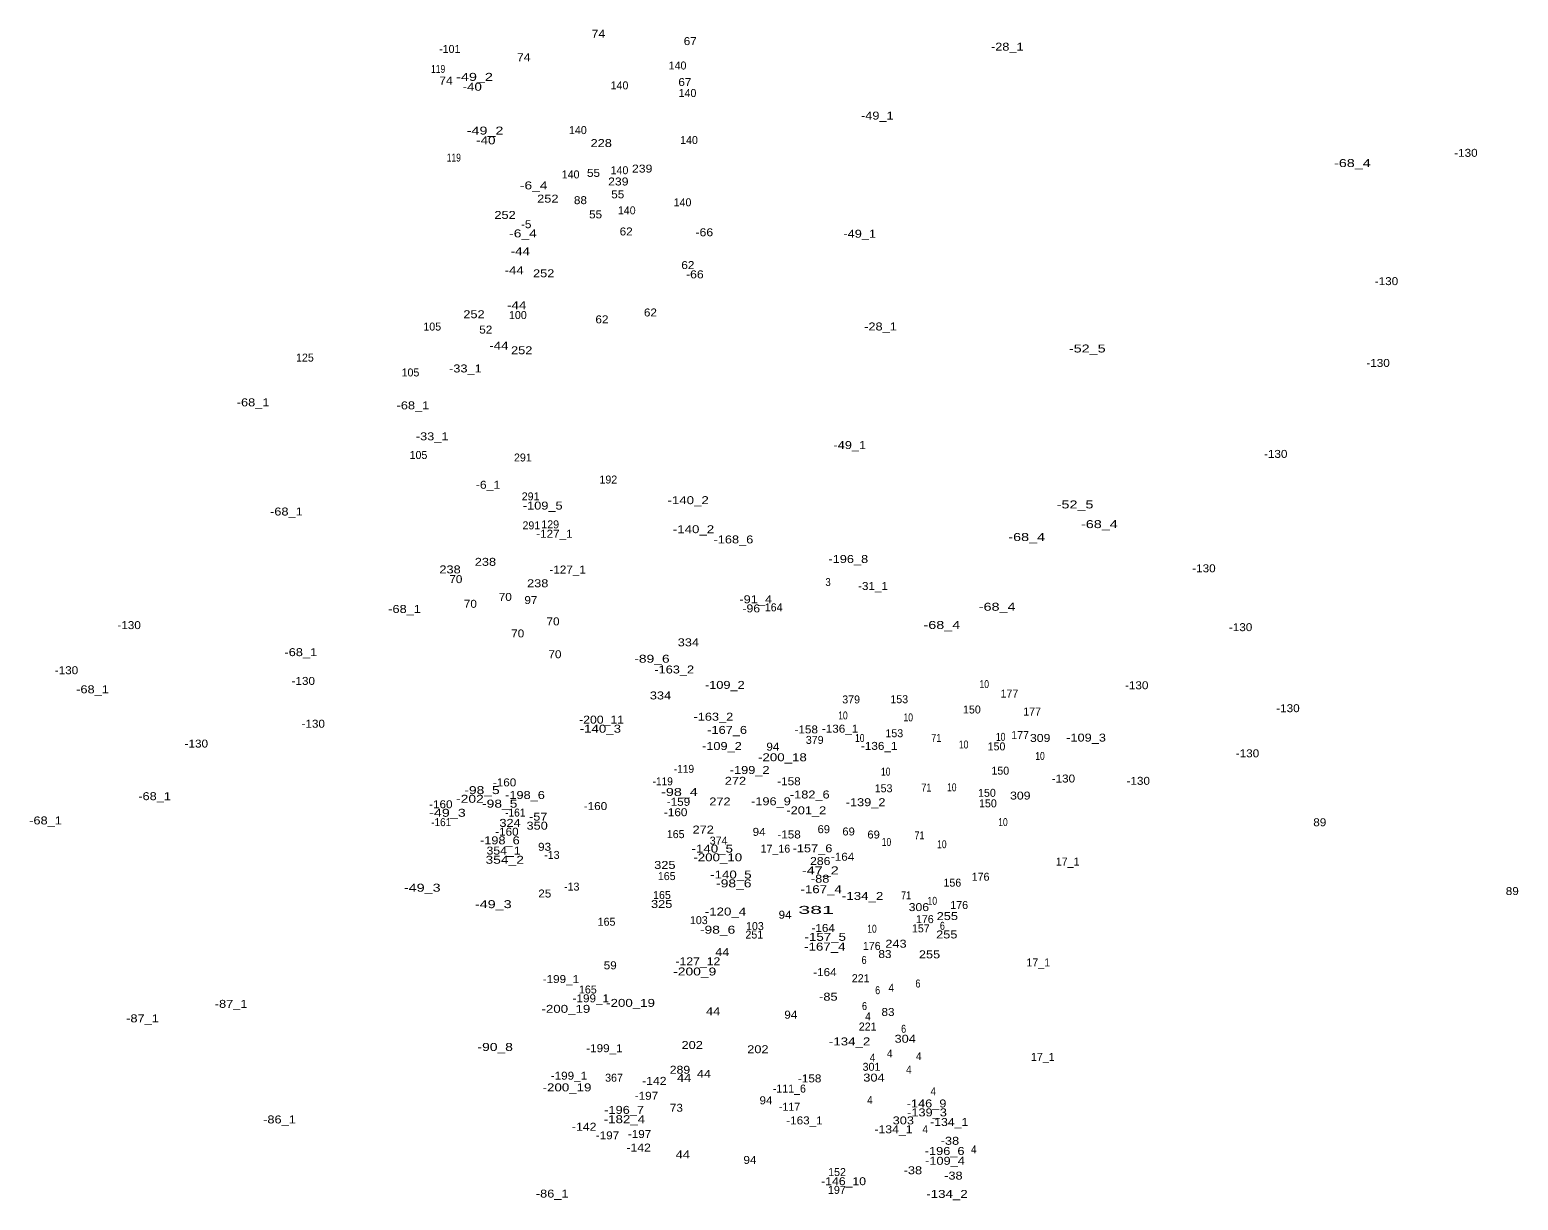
# Model space of a CAD drawing. Extents: x -662996 to -659766, y -998554 to -993949.
# Drawn here: x -661831 to -661083, y -996273 to -995685 of the extents above; entities that cross this region are included whole.
import ezdxf
from ezdxf.enums import TextEntityAlignment as Align

# ---------------------------------------------------------------- set-up
doc = ezdxf.new("R2010")
doc.units = 0
doc.header["$LTSCALE"] = 1.6
doc.layers.add('24', color=7, linetype='Continuous')

msp = doc.modelspace()

# ---------------------------------------------------------------- texts
at = {"layer": '24'}
for s, width, p in [('74', 1.15, (-661545.52, -995689.19)), ('67', 1.1, (-661499.35, -995692.88)), ('-28_1', 1.2, (-661339.949, -995695.69)), ('74', 1.15, (-661583.06, -995700.99)), ('119', 0.8, (-661626.101, -995706.87)), ('-49_2', 1.35, (-661607.79, -995710.85)), ('74', 1.15, (-661622.13, -995712.7)), ('-40', 1.25, (-661608.94, -995715.84)), ('67', 1.1, (-661502.04, -995713.44)), ('-49_1', 1.2, (-661405.3, -995730.32)), ('-49_2', 1.35, (-661602.5, -995737.84)), ('-40', 1.25, (-661602.11, -995742.74)), ('228', 1.2, (-661544.1, -995744.12)), ('-130', 1.1, (-661109.37, -995749.03)), ('119', 0.8, (-661618.221, -995751.43)), ('239', 1.15, (-661523.51, -995756.95)), ('-68_4', 1.35, (-661166.44, -995754.17)), ('55', 1.1, (-661547.98, -995759.12)), ('239', 1.15, (-661535.51, -995763.43)), ('-6_4', 1.3, (-661578.05, -995765.4)), ('252', 1.2, (-661570.939, -995772.05)), ('55', 1.1, (-661535.79, -995769.87)), ('88', 1.1, (-661554.549, -995772.82)), ('252', 1.2, (-661592.449, -995780.24)), ('-5', 1.1, (-661581.8, -995784.9)), ('55', 1.1, (-661546.929, -995779.96)), ('-6_4', 1.3, (-661583.43, -995789.51)), ('62', 1.1, (-661531.56, -995788.54)), ('-66', 1.15, (-661492.27, -995788.95)), ('-49_1', 1.2, (-661414.14, -995789.69)), ('-44', 1.25, (-661584.78, -995798.52)), ('-44', 1.25, (-661587.85, -995808.03)), ('252', 1.2, (-661573.03, -995809.57)), ('62', 1.1, (-661500.55, -995805.44)), ('-66', 1.15, (-661497.03, -995810.1)), ('-130', 1.1, (-661149.301, -995813.51)), ('252', 1.2, (-661608.069, -995830.14)), ('-44', 1.25, (-661586.6, -995825.61)), ('62', 1.1, (-661519.37, -995829.26)), ('52', 1.1, (-661602.14, -995837.85)), ('62', 1.1, (-661543.75, -995832.72)), ('-28_1', 1.2, (-661403.699, -995836.29)), ('-44', 1.25, (-661595.53, -995845.87)), ('252', 1.2, (-661584.079, -995848.24)), ('-52_5', 1.35, (-661299.73, -995847.36)), ('-33_1', 1.2, (-661612.39, -995857.39)), ('-130', 1.1, (-661153.53, -995854.62)), ('-68_1', 1.2, (-661719.13, -995874.42)), ('-68_1', 1.2, (-661638.78, -995875.94)), ('-33_1', 1.2, (-661629.1, -995891.49)), ('-49_1', 1.2, (-661419.13, -995895.89)), ('-130', 1.1, (-661204.99, -995900.33)), ('-6_1', 1.15, (-661601, -995915.84)), ('-68_1', 1.2, (-661702.38, -995929.28)), ('-109_5', 1.2, (-661573.51, -995926.31)), ('-140_2', 1.25, (-661500.41, -995923.58)), ('-52_5', 1.35, (-661305.87, -995925.73)), ('-68_4', 1.35, (-661293.64, -995935.62)), ('-127_1', 1.1, (-661567.64, -995940.45)), ('-140_2', 1.25, (-661497.72, -995938.18)), ('-168_6', 1.2, (-661477.64, -995943.31)), ('-68_4', 1.35, (-661330.19, -995942.1)), ('238', 1.2, (-661620.11, -995958.38)), ('238', 1.2, (-661602.309, -995954.57)), ('-127_1', 1.1, (-661560.981, -995958.43)), ('-196_8', 1.2, (-661419.89, -995953.15)), ('-130', 1.1, (-661241.081, -995957.82)), ('70', 1.1, (-661617.19, -995963.26)), ('238', 1.2, (-661576.03, -995965.33)), ('3', 0.9, (-661430.049, -995964.72)), ('-31_1', 1.1, (-661407.459, -995966.71)), ('70', 1.1, (-661592.33, -995972.2)), ('97', 1.1, (-661579.46, -995973.78)), ('-91_4', 1.2, (-661466.44, -995973.4)), ('-68_1', 1.2, (-661642.971, -995978.25)), ('70', 1.1, (-661609.89, -995975.65)), ('-96', 1.15, (-661468.669, -995977.96)), ('-68_4', 1.35, (-661345.05, -995977.15)), ('-130', 1.1, (-661781.451, -995986.37)), ('70', 1.1, (-661568.33, -995984.49)), ('-68_4', 1.35, (-661372.84, -995986.29)), ('-130', 1.1, (-661222.65, -995987.4)), ('70', 1.1, (-661586.09, -995990.54)), ('334', 1.2, (-661500.29, -995995.01)), ('-68_1', 1.2, (-661695.14, -995999.96)), ('70', 1.1, (-661567.37, -996001.01)), ('-89_6', 1.3, (-661518.6, -996003.26)), ('-130', 1.1, (-661812.941, -996009.03)), ('-163_2', 1.2, (-661507.4, -996008.66)), ('-68_1', 1.2, (-661799.861, -996018.63)), ('-130', 1.1, (-661693.9, -996014.41)), ('-109_2', 1.2, (-661481.961, -996016.41)), ('10', 0.8, (-661351.53, -996016.01)), ('-130', 1.1, (-661274.88, -996016.6)), ('334', 1.2, (-661514.299, -996021.71)), ('-200_11', 1.15, (-661543.92, -996033.87)), ('-163_2', 1.2, (-661487.721, -996032.39)), ('10', 0.8, (-661422.57, -996031.76)), ('10', 0.8, (-661389.74, -996032.73)), ('-130', 1.1, (-661198.841, -996028.12)), ('-130', 1.1, (-661688.9, -996035.92)), ('-140_3', 1.25, (-661544.53, -996038.42)), ('-167_6', 1.2, (-661480.799, -996039.03)), ('-158', 1.1, (-661441.03, -996038.78)), ('-136_1', 1.1, (-661424.03, -996038.41)), ('-130', 1.1, (-661747.66, -996045.91)), ('-109_2', 1.2, (-661483.421, -996047.13)), ('94', 1.1, (-661457.8, -996047.45)), ('10', 0.8, (-661414.12, -996043.1)), ('-136_1', 1.1, (-661404.351, -996047.06)), ('71', 0.85, (-661375.66, -996043.04)), ('10', 0.8, (-661361.9, -996046.36)), ('10', 0.8, (-661343.27, -996042.52)), ('309', 1.15, (-661323.41, -996043.08)), ('-109_3', 1.2, (-661300.351, -996042.9)), ('-200_18', 1.25, (-661453, -996052.77)), ('10', 0.8, (-661323.49, -996052.12)), ('-130', 1.1, (-661219.191, -996050.79)), ('-119', 0.95, (-661502.51, -996058.58)), ('-199_2', 1.2, (-661469.47, -996059.18)), ('10', 0.8, (-661401.06, -996060)), ('-130', 1.1, (-661311.74, -996063.47)), ('-98_5', 1.3, (-661604.04, -996069.29)), ('-160', 1.1, (-661592.69, -996065.4)), ('-119', 0.95, (-661513.17, -996064.87)), ('-98_4', 1.35, (-661504.77, -996070.22)), ('272', 1.2, (-661476.61, -996064.62)), ('-158', 1.1, (-661449.711, -996064.84)), ('-182_6', 1.2, (-661439.25, -996071.49)), ('71', 0.85, (-661380.65, -996068.01)), ('10', 0.8, (-661367.85, -996067.88)), ('-130', 1.1, (-661274.111, -996064.62)), ('-68_1', 1.2, (-661768.64, -996072.34)), ('-160', 1.1, (-661624.75, -996076.4)), ('-202', 1.3, (-661610.12, -996073.65)), ('-98_5', 1.3, (-661595.13, -996076.09)), ('-198_6', 1.2, (-661582.43, -996071.75)), ('-160', 1.1, (-661546.99, -996077.31)), ('-159', 1.1, (-661505.27, -996075.16)), ('272', 1.2, (-661484.41, -996075)), ('-196_9', 1.2, (-661458.78, -996074.9)), ('-139_2', 1.2, (-661411.191, -996075.36)), ('309', 1.15, (-661333.41, -996072.03)), ('-68_1', 1.2, (-661823.481, -996084.53)), ('-49_3', 1.35, (-661621.42, -996080.68)), ('-161', 0.95, (-661624.56, -996085.38)), ('324', 1.2, (-661589.939, -996085.76)), ('-161', 0.95, (-661587.31, -996080.58)), ('-57', 1.2, (-661575.77, -996082.62)), ('-160', 1.1, (-661506.67, -996080.39)), ('-201_2', 1.2, (-661441, -996079.44)), ('10', 0.8, (-661342.12, -996085.35)), ('89', 1.1, (-661182.83, -996085.44)), ('-160', 1.1, (-661591.53, -996090.18)), ('350', 1.2, (-661576.309, -996087.15)), ('272', 1.2, (-661492.82, -996089.1)), ('94', 1.1, (-661464.72, -996090.25)), ('-158', 1.1, (-661449.671, -996091.57)), ('69', 1.05, (-661432.21, -996088.92)), ('69', 1.05, (-661419.73, -996090.07)), ('69', 1.05, (-661407.15, -996091.61)), ('71', 0.85, (-661384.101, -996092.02)), ('-198_6', 1.2, (-661595.07, -996094.52)), ('354_1', 1.15, (-661593.199, -996099.68)), ('93', 1.1, (-661572.58, -996097.77)), ('-140_5', 1.25, (-661488.28, -996098.69)), ('-157_6', 1.2, (-661437.89, -996098.53)), ('10', 0.8, (-661400.68, -996095.34)), ('10', 0.8, (-661372.84, -996096.49)), ('354_2', 1.3, (-661592.62, -996104.29)), ('325', 1.2, (-661512.1, -996106.89)), ('-200_10', 1.25, (-661485.51, -996103.05)), ('286', 1.15, (-661434, -996104.92)), ('-164', 1.1, (-661422.76, -996102.76)), ('-140_5', 1.25, (-661478.919, -996111.7)), ('-98_6', 1.3, (-661477.45, -996116.14)), ('-47_2', 1.35, (-661433.929, -996109.63)), ('-88', 1.2, (-661434.03, -996113.81)), ('-49_3', 1.35, (-661634.09, -996118.33)), ('25', 1.1, (-661572.48, -996121.24)), ('-167_4', 1.25, (-661433.52, -996119.08)), ('-134_2', 1.25, (-661412.689, -996122.48)), ('71', 0.85, (-661390.821, -996122.17)), ('89', 1.1, (-661086.06, -996120.02)), ('-49_3', 1.35, (-661598.38, -996126.59)), ('325', 1.2, (-661513.709, -996126.51)), ('-120_4', 1.25, (-661481.63, -996130.3)), ('381', 2, (-661436.057, -996129.48)), ('306', 1.15, (-661384.4, -996128.08)), ('10', 0.8, (-661377.64, -996124.92)), ('94', 1.1, (-661451.66, -996131.89)), ('-164', 1.1, (-661432.51, -996138.58)), ('255', 1.2, (-661370.09, -996132.59)), ('6', 0.85, (-661372.57, -996137.46)), ('-98_6', 1.3, (-661485.6, -996139.44)), ('-157_5', 1.25, (-661431.46, -996143.03)), ('10', 0.8, (-661407.98, -996138.94)), ('255', 1.2, (-661370.37, -996141.82)), ('44', 1.2, (-661483.22, -996150.64)), ('-167_4', 1.25, (-661431.691, -996147.93)), ('83', 1.1, (-661401.459, -996151.67)), ('243', 1.2, (-661395.91, -996146.48)), ('255', 1.2, (-661379.04, -996151.82)), ('59', 1.1, (-661539.58, -996157.33)), ('-200_9', 1.3, (-661497.091, -996160.43)), ('-127_12', 1.15, (-661495.51, -996155.32)), ('-164', 1.1, (-661431.64, -996160.76)), ('6', 0.85, (-661411.94, -996154.65)), ('-199_1', 1.1, (-661564.38, -996164.24)), ('4', 0.95, (-661398.27, -996168.6)), ('6', 0.85, (-661384.86, -996166.47)), ('-199_1', 1.1, (-661549.33, -996173.91)), ('-200_19', 1.25, (-661529.361, -996176.21)), ('-85', 1.2, (-661429.91, -996173.11)), ('6', 0.85, (-661405.12, -996169.83)), ('-87_1', 1.2, (-661730.17, -996176.7)), ('-200_19', 1.25, (-661561.87, -996179.2)), ('44', 1.2, (-661487.83, -996180.41)), ('94', 1.1, (-661448.78, -996182.14)), ('6', 0.85, (-661411.74, -996177.8)), ('4', 0.95, (-661409.99, -996183.01)), ('83', 1.1, (-661399.919, -996180.77)), ('-87_1', 1.2, (-661774.72, -996183.99)), ('6', 0.85, (-661392.06, -996189.23)), ('-90_8', 1.3, (-661597.41, -996198.36)), ('202', 1.2, (-661498.37, -996197.39)), ('-134_2', 1.25, (-661419.22, -996195.58)), ('304', 1.2, (-661391.27, -996194.23)), ('-199_1', 1.1, (-661542.49, -996198.98)), ('202', 1.2, (-661465.34, -996199.5)), ('4', 0.95, (-661407.689, -996203.69)), ('4', 0.95, (-661399.04, -996201.64)), ('4', 0.95, (-661384.449, -996202.98)), ('-199_1', 1.1, (-661560.33, -996212.8)), ('289', 1.15, (-661504.51, -996209.81)), ('44', 1.2, (-661492.44, -996211.87)), ('4', 0.95, (-661389.439, -996209.71)), ('-200_19', 1.25, (-661561.291, -996218.67)), ('-142', 1.15, (-661517.42, -996215.4)), ('44', 1.2, (-661502.42, -996213.89)), ('-158', 1.1, (-661439.301, -996214.17)), ('304', 1.2, (-661406.97, -996213.75)), ('4', 0.95, (-661377.15, -996220.65)), ('-197', 1.1, (-661521.37, -996222.9)), ('94', 1.1, (-661461.26, -996225.17)), ('4', 0.95, (-661409.03, -996225.07)), ('-146_9', 1.2, (-661380.54, -996226.75)), ('-86_1', 1.2, (-661705.861, -996234.79)), ('-182_4', 1.25, (-661532.439, -996234.66)), ('-196_7', 1.2, (-661532.59, -996229.98)), ('73', 1.1, (-661506.32, -996228.91)), ('-163_1', 1.1, (-661441.921, -996235.26)), ('303', 1.2, (-661392.22, -996235.27)), ('-139_3', 1.2, (-661380.321, -996231.24)), ('-134_1', 1.15, (-661369.14, -996236.09)), ('-142', 1.15, (-661552.66, -996238.45)), ('-197', 1.1, (-661540.949, -996242.78)), ('-197', 1.1, (-661524.84, -996242.11)), ('-134_1', 1.15, (-661397.179, -996239.74)), ('4', 0.95, (-661381.189, -996239.67)), ('-142', 1.15, (-661525.3, -996248.91)), ('-196_6', 1.2, (-661371.449, -996250.63)), ('-38', 1.2, (-661368.78, -996245.52)), ('4', 0.95, (-661356.799, -996249.85)), ('44', 1.2, (-661503.09, -996252.39)), ('94', 1.1, (-661469.32, -996255.13)), ('-109_4', 1.2, (-661371.28, -996255.57)), ('-146_10', 1.15, (-661422.26, -996265.83)), ('-38', 1.2, (-661387.41, -996260.32)), ('-38', 1.2, (-661367.05, -996263.01)), ('-86_1', 1.2, (-661568.76, -996272.06)), ('-134_2', 1.25, (-661370.26, -996272.22))]:
    msp.add_text(s, height=4, dxfattribs=dict(at, width=width)).set_placement(p, align=Align.CENTER)
for s, p in [('-101', (-661620.24, -995696.82)), ('140', (-661505.72, -995705.14)), ('140', (-661534.91, -995715.13)), ('140', (-661500.73, -995718.97)), ('140', (-661555.84, -995737.6)), ('140', (-661499.959, -995742.59)), ('140', (-661559.48, -995759.88)), ('140', (-661534.91, -995757.77)), ('140', (-661531.26, -995777.94)), ('140', (-661503.23, -995773.9)), ('100', (-661586.01, -995830.56)), ('105', (-661629.06, -995836.34)), ('125', (-661693.079, -995851.93)), ('105', (-661640.01, -995859.39)), ('105', (-661635.98, -995900.88)), ('291', (-661583.5, -995902.14)), ('192', (-661540.53, -995913.2)), ('291', (-661579.601, -995921.67)), ('291', (-661579.221, -995936.24)), ('129', (-661569.75, -995935.74)), ('164', (-661457.41, -995977.43)), ('379', (-661418.448, -996023.71)), ('153', (-661394.26, -996023.61)), ('177', (-661338.89, -996020.78)), ('150', (-661357.75, -996028.77)), ('177', (-661327.46, -996029.8)), ('153', (-661396.75, -996040.7)), ('379', (-661436.768, -996044.05)), ('150', (-661345.37, -996047.31)), ('177', (-661333.51, -996041.62)), ('150', (-661343.45, -996059.51)), ('153', (-661402.13, -996068.36)), ('150', (-661350.17, -996070.65)), ('150', (-661349.69, -996075.93)), ('165', (-661506.66, -996091.41)), ('374', (-661485.077, -996094.66)), ('17_16', (-661456.53, -996098.7)), ('-13', (-661568.9, -996101.84)), ('17_1', (-661309.6, -996105.19)), ('165', (-661511.171, -996112.49)), ('156', (-661367.561, -996115.79)), ('176', (-661353.37, -996112.81)), ('-13', (-661558.91, -996117.78)), ('165', (-661513.581, -996122.01)), ('176', (-661364.12, -996127.03)), ('165', (-661541.421, -996135.44)), ('103', (-661495.05, -996134.63)), ('103', (-661466.83, -996137.61)), ('157', (-661383.431, -996138.77)), ('176', (-661381.4, -996134.13)), ('251', (-661467.13, -996141.88)), ('176', (-661408.09, -996147.58)), ('17_1', (-661324.38, -996155.9)), ('221', (-661413.65, -996163.81)), ('165', (-661550.821, -996169.49)), ('221', (-661410.13, -996188.09)), ('17_1', (-661322.08, -996203.34)), ('301', (-661408.22, -996208.33)), ('367', (-661537.678, -996213.81)), ('-111_6', (-661449.52, -996219.28)), ('-117', (-661449.42, -996228.41)), ('152', (-661425.54, -996261.23)), ('197', (-661425.63, -996270.18))]:
    msp.add_text(s, height=4, dxfattribs=at).set_placement(p, align=Align.CENTER)

doc.saveas('drawing.dxf')
